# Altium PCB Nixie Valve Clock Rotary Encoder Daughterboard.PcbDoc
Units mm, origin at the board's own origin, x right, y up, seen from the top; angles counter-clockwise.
Board outline 16 x 41.76 mm, 2 copper layers (Top Layer, Bottom Layer), stack 1.57 mm thick; 2 components, 6 nets, 17 pads, 0 vias.
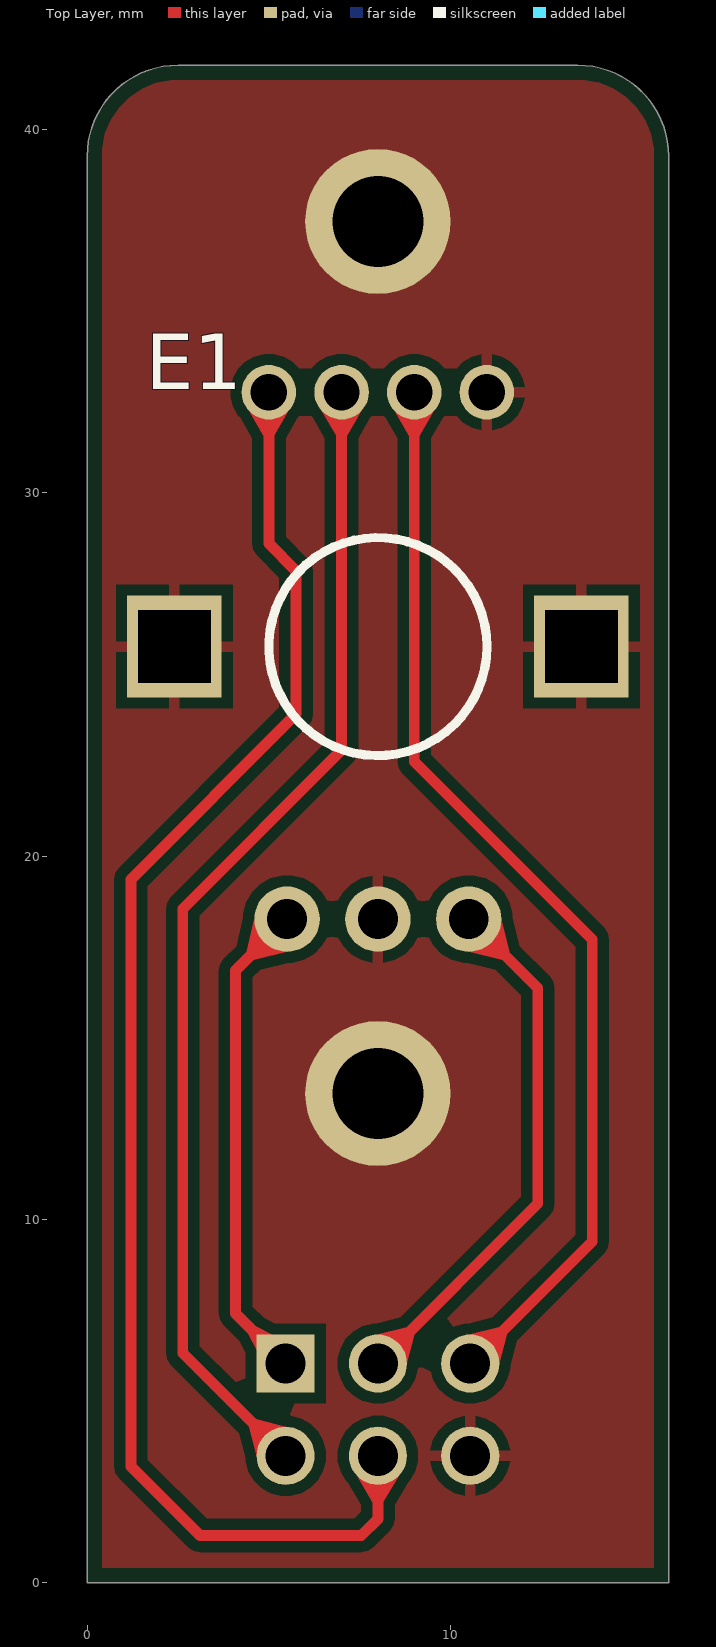
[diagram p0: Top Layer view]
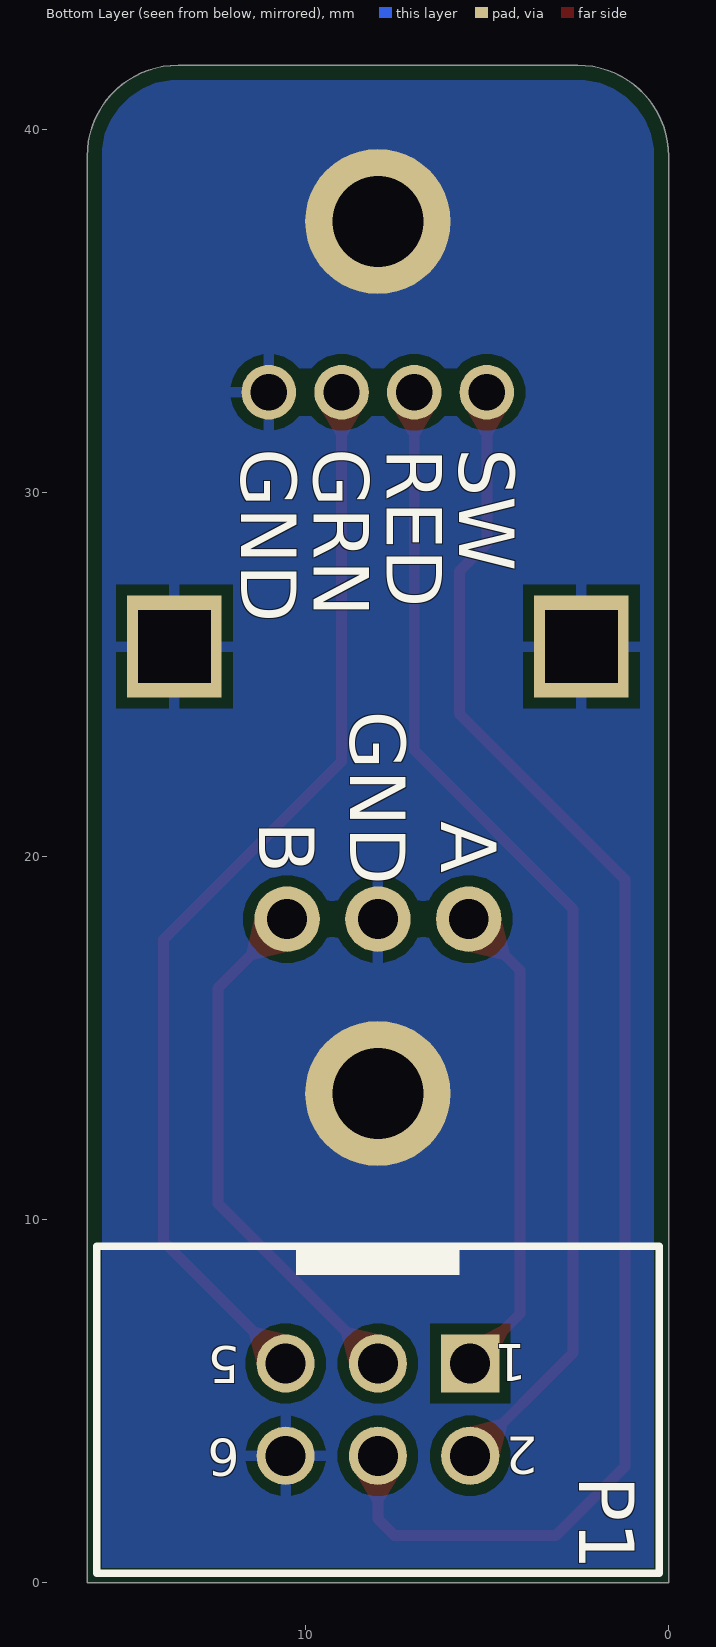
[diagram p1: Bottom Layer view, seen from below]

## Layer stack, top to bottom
Top Solder: solder mask 0.01, SM-001, Dk 4
Top Layer: signal copper 0.035
Dielectric 1: core 1.5, Core-043, Dk 4.3
Bottom Layer: signal copper 0.035
Bottom Solder: solder mask 0.01, SM-001, Dk 4

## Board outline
0,0 16,0 16,39.265 ccw(c13.5,39.265) 13.5,41.765 2.5,41.765 ccw(c2.5,39.265) 0,39.265

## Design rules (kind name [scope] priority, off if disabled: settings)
BoardOutlineClearance [All] p1: gap=0.4 ignorepadtopadclearanceinfootprint=FALSE
Clearance Clearance_GND_Planes [InPoly AND InNet('GND')] p1: gap=0.3 ignorepadtopadclearanceinfootprint=FALSE
Clearance Clearance_NPTH_to_Track [IsThruPin AND NOT(PadIsPlated) vs IsTrack] p2: gap=0.2 ignorepadtopadclearanceinfootprint=FALSE
Clearance Clearance_PTH_to_Track [IsTrack vs IsThruPin AND PadIsPlated] p3: gap=0.28 ignorepadtopadclearanceinfootprint=FALSE
Clearance Clearance_Via_to_Track [IsVia vs IsTrack] p4: gap=0.2 ignorepadtopadclearanceinfootprint=FALSE
Clearance Clearance_SMD_Pad_to_SMD_Pad [IsPad AND NOT(IsThruPin) vs IsPad AND NOT(IsThruPin)] p5: gap=0.15 ignorepadtopadclearanceinfootprint=FALSE
Clearance Clearance_Pad_to_Track [IsPad vs IsTrack] p6: gap=0.1 ignorepadtopadclearanceinfootprint=FALSE
Clearance Clearance_Inner_Cu_to_PTH [OnLayer('Inner 1') OR OnLayer('Inner 2') vs IsThruPin AND PadIsPlated] p7: gap=0.1 ignorepadtopadclearanceinfootprint=FALSE
Clearance Clearance_Inner_Cu_to_Vias [IsVia vs OnLayer('Inner 1') OR OnLayer('Inner 2')] p8: gap=1.95 ignorepadtopadclearanceinfootprint=FALSE
Clearance Clearance_Same_Nets [IsTrack vs IsTrack] p9: gap=0.25 ignorepadtopadclearanceinfootprint=FALSE
Clearance Minimum_Clearance [All] p10: gap=0.1 ignorepadtopadclearanceinfootprint=FALSE
Clearance [All] p11: gap=0.3 ignorepadtopadclearanceinfootprint=FALSE
HoleSize "Minimum Hole Size PTH" [(IsThruPin AND IsPad And PadIsPlated)] p1: absolutevalues=TRUE maxlimit=5 minlimit=0.3 maxpercent=80.000 minpercent=20.000
HoleSize "Minimum Hole Size VIA" [IsVia] p2: absolutevalues=TRUE maxlimit=5 minlimit=0.15 maxpercent=80.000 minpercent=20.000
HoleSize "Minimum Hole Size NPTH" [(IsThruPin AND IsPad And (NOT PadIsPlated))] p3: absolutevalues=TRUE maxlimit=5 minlimit=0.5 maxpercent=80.000 minpercent=20.000
HoleSize [All] p4: absolutevalues=TRUE maxlimit=7.62 minlimit=0.254 maxpercent=80.000 minpercent=20.000
HoleToHoleClearance ViaHoleToHoleClearance [IsVia vs IsVia] p1: gap=0.2 allowstackedmicrovias=TRUE
HoleToHoleClearance PadHoleToHoleClearance [IsPad vs IsPad] p2: gap=0.45 allowstackedmicrovias=TRUE
HoleToHoleClearance [All] p3: gap=0.254 allowstackedmicrovias=TRUE
MinimumAnnularRing PTH_MinimumAnnularRing [(IsThruPin AND IsPad And PadIsPlated)] p1: minimumring=0.2
MinimumAnnularRing VIA_MinimumAnnularRing [IsVia] p2: minimumring=0.05
MinimumAnnularRing NPTH_MinimumAnnularRing [(IsThruPin AND IsPad And (NOT PadIsPlated))] p3: minimumring=0.45
MinimumAnnularRing [All] p4: minimumring=0.2
MinimumSolderMaskSliver [All] p1: minsoldermaskwidth=0.1
PolygonConnect PolygonConnect_GND_Vias_And_Pads [(IsVia AND InNet('GND')) OR (IsPad AND IsThruPin AND NOT(InAnyComponent) AND InNet('GND')) vs IsPoly AND InNet('GND')] p1: connectstyle=Direct reliefconductorwidth=0.3 reliefentries=4 polygonreliefangle="90 Angle" airgapwidth=0.3
PolygonConnect [All] p2: connectstyle=Relief reliefconductorwidth=0.3 reliefentries=4 polygonreliefangle="90 Angle" airgapwidth=0.3
RoutingVias [All] p1: holewidth=0.711 width=1.27 viastyle="Through Hole" minholewidth=0.711 minwidth=1.27 maxholewidth=0.711 maxwidth=1.27
SMDNeckDown [All] p1: percent=100.000
SilkToSilkClearance [All] p1: silktosilkclearance=0.1
SilkToSolderMaskClearance [All] p1: minsilkscreentomaskgap=0 clearancetoexposedcopper=FALSE
SilkToSolderMaskClearance SilkscreenOverComponentPads [IsPad] p2: minsilkscreentomaskgap=0.254 clearancetoexposedcopper=TRUE
SolderMaskExpansion SolderMaskExpansion_Tented_Vias [IsVia] p1: expansion=0.1 istentingtop=TRUE
SolderMaskExpansion [All] p2: expansion=0.1 istentingtop=FALSE
SupplyNets "Schematic Supply Nets_2" [InNet('+3V3')] p1: voltage=0.000
SupplyNets "Schematic Supply Nets_4" [InNet('GND')] p2: voltage=0.000
SupplyNets "Schematic Supply Nets_3" [InNet('+9V')] p3: voltage=0.000
SupplyNets "Schematic Supply Nets_1" [InNet('+HV')] p4: voltage=0.000
SupplyNets "Schematic Supply Nets" [InNet('+100V')] p5: voltage=0.000
Width "Minimum Width" [All] p1: maxlimit=3 minlimit=0.1 preferedwidth=0.3
25 further rules are at their usual default settings.

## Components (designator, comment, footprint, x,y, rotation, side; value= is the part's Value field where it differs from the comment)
E1 "4-1879314-5" 4-1879314-5-Footprint-1 8,18.265 r0 top value=25kΩ
P1 "61200621621" 61200621621 8,4.765 r0 bottom

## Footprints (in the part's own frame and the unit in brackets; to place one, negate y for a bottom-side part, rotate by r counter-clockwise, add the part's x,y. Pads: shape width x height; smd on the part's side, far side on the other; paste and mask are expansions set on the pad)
4-1879314-5-Footprint-1 [mm]
  round 1.5 hole 1: 1(3,14.5) 2(1,14.5) 3(-1,14.5) 4(-3,14.5)
  round 1.8 hole 1.1: A(-2.5,0) B(2.5,0) C(0,0)
  rect 2.6x2.8 hole 2 square: MP0(-5.6,7.5) MP1(5.6,7.5)
  silkscreen extent -3,4.5 3,10.5, body extent -7,-0.15 7,14.65, height 25
61200621621 [mm] "6 pins, straight, gold plating"
  rect 1.6x1.6 hole 1.1: 1(-2.54,-1.27)
  round 1.6 hole 1.1: 2(-2.54,1.27) 3(0,-1.27) 4(0,1.27) 5(2.54,-1.27) 6(2.54,1.27)
  silkscreen extent -7.74,-4.5 7.74,4.5, body extent -7.64,-4.43 7.64,4.75, height 9.13

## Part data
E1: library part CMP-010-00025-2, "Incremental Encoder, Mechanical, 24Ppr Rohs Compliant: Yes", Color="Green, Red", Max Operating Temperature=85°C, Max Supply Voltage=5V, Min Operating Temperature=-40°C
P1: library part CMP-002-00109-1, "Board Connector, 6 Contact(s), 2 Row(s), Male, Straight, Solder Terminal", Flammability Rating="UL94 V-0"

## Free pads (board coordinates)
  round 4 hole 2.5: 1(8,37.465) 2(8,13.465)

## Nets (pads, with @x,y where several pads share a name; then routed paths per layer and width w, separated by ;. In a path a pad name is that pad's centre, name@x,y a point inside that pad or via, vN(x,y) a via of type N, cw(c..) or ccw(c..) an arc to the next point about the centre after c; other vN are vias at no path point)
ENC_GRN_LED: E1.2 P1.5 | length 30.2
  Top Layer w0.3: E1.2 9,22.6 13.9,17.7 13.9,9.395 P1.5
ENC_RED_LED: E1.3 P1.2 | length 32.3
  Top Layer w0.3: P1.2 2.629,6.326 2.629,18.544 7,22.916 E1.3
ENC_SW: E1.4 P1.4 | length 41.3
  Top Layer w0.3: E1.4 5,28.6 5.75,27.85 5.75,23.906 1.2,19.356 1.2,3.2 3.1,1.3 7.542,1.3 8,1.758 P1.4
ENCDR_A: E1.A P1.1 | length 13.4
  Top Layer w0.3: P1.1 4.084,7.41 4.084,16.849 E1.A
ENCDR_B: E1.B P1.3 | length 14.8
  Top Layer w0.3: P1.3 12.4,10.435 12.4,16.365 E1.B
GND: E1.1 E1.C E1.MP0 E1.MP1 P1.6 pad.1 pad.2

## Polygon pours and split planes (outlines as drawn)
GND on Top Layer "TOP_GND" (solid, remove dead copper, pour order 0): 0,0 16,0 16,39.265 ccw(c13.5,39.265) 13.5,41.765 2.5,41.765 ccw(c2.5,39.265) 0,39.265
GND on Bottom Layer "GND_BOTTOM" (solid, remove dead copper, pour order 1): 0,0 16,0 16,39.265 ccw(c13.5,39.265) 13.5,41.765 2.5,41.765 ccw(c2.5,39.265) 0,39.265

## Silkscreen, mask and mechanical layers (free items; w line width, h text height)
Bottom Overlay:
  text "SW" at 5.762,31.217 h1.52 r90
  text "RED" at 7.762,31.217 h1.52 r90
  text "GRN" at 9.762,31.217 h1.52 r90
  text "GND" at 11.762,31.217 h1.52 r90
  text "GND" at 8.762,24.001 h1.52 r90
  text "A" at 6.262,20.954 h1.52 r90
  text "B" at 11.262,20.954 h1.52 r90
Mechanical 1:
  lines w0.254: 0,0 0,39.265 cw(c2.5,39.265) 2.5,41.765 13.5,41.765 cw(c13.5,39.265) 16,39.265 16,0 0,0
  lines w0.381: 20.776,3.276 31.188,3.276 64.96,3.276 81.72,3.276 98.226,3.276 112.7,3.276 ; 20.776,6.324 31.188,6.324 64.96,6.324 81.72,6.324 98.226,6.324 112.7,6.324 ; 20.776,9.372 31.188,9.372 64.96,9.372 81.72,9.372 98.226,9.372 112.7,9.372 ; 20.776,12.42 31.188,12.42 64.96,12.42 81.72,12.42 98.226,12.42 112.7,12.42 ; 20.776,15.468 31.188,15.468 64.96,15.468 81.72,15.468 98.226,15.468 112.7,15.468 ; 20.776,18.516 31.188,18.516 64.96,18.516 81.72,18.516 98.226,18.516 112.7,18.516 ; 20.776,21.564 31.188,21.564 64.96,21.564 81.72,21.564 98.226,21.564 112.7,21.564 ; 20.776,24.612 31.188,24.612 64.96,24.612 81.72,24.612 98.226,24.612 112.7,24.612 ; 20.776,27.66 112.7,27.66 ; 31.188,30.708 31.188,0.228 ; 64.96,30.708 64.96,0.228 ; 81.72,30.708 81.72,0.228 ; 98.226,30.708 98.226,0.228 ; 31.188,0.228 20.776,0.228 20.776,30.708 112.7,30.708 112.7,0.228 98.226,0.228 ; 31.188,0.228 64.96,0.228 ; 64.96,0.228 81.72,0.228 ; 81.72,0.228 98.226,0.228
  text "Use 2x M2 (2.1mm ID x 4mm OD) 6mm length spacer between this  / daughterboard and motherboard, and 2x M2 Cap Head 12mm screws" at 20.5,31.247 h1.52
  text "Layer" at 22.554,28.422 h1.52
  text "Name" at 32.966,28.422 h1.52
  text "Material" at 66.738,28.422 h1.52
  text "Thickness" at 83.498,28.422 h1.52
  text "Constant" at 100.004,28.422 h1.52
  text "Top Overlay" at 32.966,25.374 h1.52
  text "Top Solder" at 32.966,22.326 h1.52
  text "SM-001" at 66.738,22.326 h1.52
  text "0.010mm" at 83.498,22.326 h1.52
  text "4" at 100.004,22.326 h1.52
  text "Top Surface Finish" at 32.966,19.278 h1.52
  text "Lead-Free" at 66.738,19.278 h1.52
  text "0.020mm" at 83.498,19.278 h1.52
  text "1" at 22.554,16.23 h1.52
  text "Top Layer" at 32.966,16.23 h1.52
  text "CF-004" at 66.738,16.23 h1.52
  text "0.035mm" at 83.498,16.23 h1.52
  text "Dielectric 1" at 32.966,13.182 h1.52
  text "Core-043" at 66.738,13.182 h1.52
  text "1.500mm" at 83.498,13.182 h1.52
  text "4.3" at 100.004,13.182 h1.52
  text "2" at 22.554,10.134 h1.52
  text "Bottom Layer" at 32.966,10.134 h1.52
  text "CF-004" at 66.738,10.134 h1.52
  text "0.035mm" at 83.498,10.134 h1.52
  text "Bottom Surface Finish" at 32.966,7.086 h1.52
  text "Lead-Free" at 66.738,7.086 h1.52
  text "0.020mm" at 83.498,7.086 h1.52
  text "Bottom Solder" at 32.966,4.038 h1.52
  text "SM-001" at 66.738,4.038 h1.52
  text "0.010mm" at 83.498,4.038 h1.52
  text "4" at 100.004,4.038 h1.52
  text "Bottom Overlay" at 32.966,0.99 h1.52
Drill Drawing:
  circle w0.254: c2.856,68.772 r0.847
  lines w0.254: 2.009,56.495 3.703,56.495 3.703,58.188 2.009,58.188 2.009,56.495 ; 2.009,60.305 2.856,60.728 3.703,60.305 3.279,61.152 3.703,61.998 2.856,61.575 2.009,61.998 2.433,61.152 2.009,60.305 ; 2.009,64.538 2.433,64.538 2.856,64.115 3.279,64.538 3.703,64.538 3.279,64.962 3.703,65.385 3.279,65.385 2.856,65.808 2.433,65.385 2.009,65.385 2.433,64.962 2.009,64.538
  lines w0.381: 0.49,55.352 187.18,55.352 ; 0.49,70.592 187.18,70.592 ; 14.483,51.542 14.483,74.402 ; 27.941,51.542 27.941,74.402 ; 55.873,51.542 55.873,74.402 ; 68.722,51.542 68.722,74.402 ; 87.361,51.542 87.361,74.402 ; 125.45,51.542 125.45,74.402 ; 140.432,51.542 140.432,74.402 ; 159.375,51.542 159.375,74.402 ; 0.49,51.542 187.18,51.542 187.18,74.402 0.49,74.402 0.49,51.542
  text "Symbol" at 2.776,71.735 h1.83
  text "Count" at 15.626,71.735 h1.83
  text "Hole Size" at 29.084,71.735 h1.83
  text "Plated" at 57.016,71.735 h1.83
  text "Hole Type" at 69.865,71.735 h1.83
  text "Drill Layer Pair" at 88.504,71.735 h1.83
  text "Via/Pad" at 126.593,71.735 h1.83
  text "Pad Shape" at 141.575,71.735 h1.83
  text "Template" at 160.518,71.735 h1.83
  text "2" at 15.626,67.925 h1.52
  text "2.000mm (78.74mil)" at 29.084,67.925 h1.52
  text "PTH" at 57.016,67.925 h1.52
  text "Rectangle" at 69.865,67.925 h1.52
  text "Top Layer - Bottom Layer" at 88.504,67.925 h1.52
  text "Pad" at 126.593,67.925 h1.52
  text "Rectangle" at 141.575,67.925 h1.52
  text "r280_260h200_220" at 160.518,67.925 h1.52
  text "2" at 15.626,64.115 h1.52
  text "2.500mm (98.43mil)" at 29.084,64.115 h1.52
  text "PTH" at 57.016,64.115 h1.52
  text "Round" at 69.865,64.115 h1.52
  text "Top Layer - Bottom Layer" at 88.504,64.115 h1.52
  text "Pad" at 126.593,64.115 h1.52
  text "Rounded" at 141.575,64.115 h1.52
  text "c400h250" at 160.518,64.115 h1.52
  text "4" at 15.626,60.305 h1.52
  text "1.000mm (39.37mil)" at 29.084,60.305 h1.52
  text "PTH" at 57.016,60.305 h1.52
  text "Round" at 69.865,60.305 h1.52
  text "Top Layer - Bottom Layer" at 88.504,60.305 h1.52
  text "Pad" at 126.593,60.305 h1.52
  text "Rounded" at 141.575,60.305 h1.52
  text "c150h100" at 160.518,60.305 h1.52
  text "9" at 15.626,56.495 h1.52
  text "1.100mm (43.31mil)" at 29.084,56.495 h1.52
  text "PTH" at 57.016,56.495 h1.52
  text "Round" at 69.865,56.495 h1.52
  text "Top Layer - Bottom Layer" at 88.504,56.495 h1.52
  text "Pad" at 126.593,56.495 h1.52
  text "(Mixed)" at 141.575,56.495 h1.52
  text "(Mixed)" at 160.518,56.495 h1.52
  text "17 Total" at 15.626,52.685 h1.52
  text "Slot definitions :" at 2.776,49.003 h1.52
  text "Routed Path Length" at 29.007,49.003 h1.52
  text "= Calculated from tool start centre position to tool end centre position." at 57.015,49.003 h1.52
  text "Hole Length" at 29.007,46.463 h1.52
  text "= Routed Path Length + Tool Size = Slot length as defined in the PCB layout" at 46.604,46.463 h1.52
